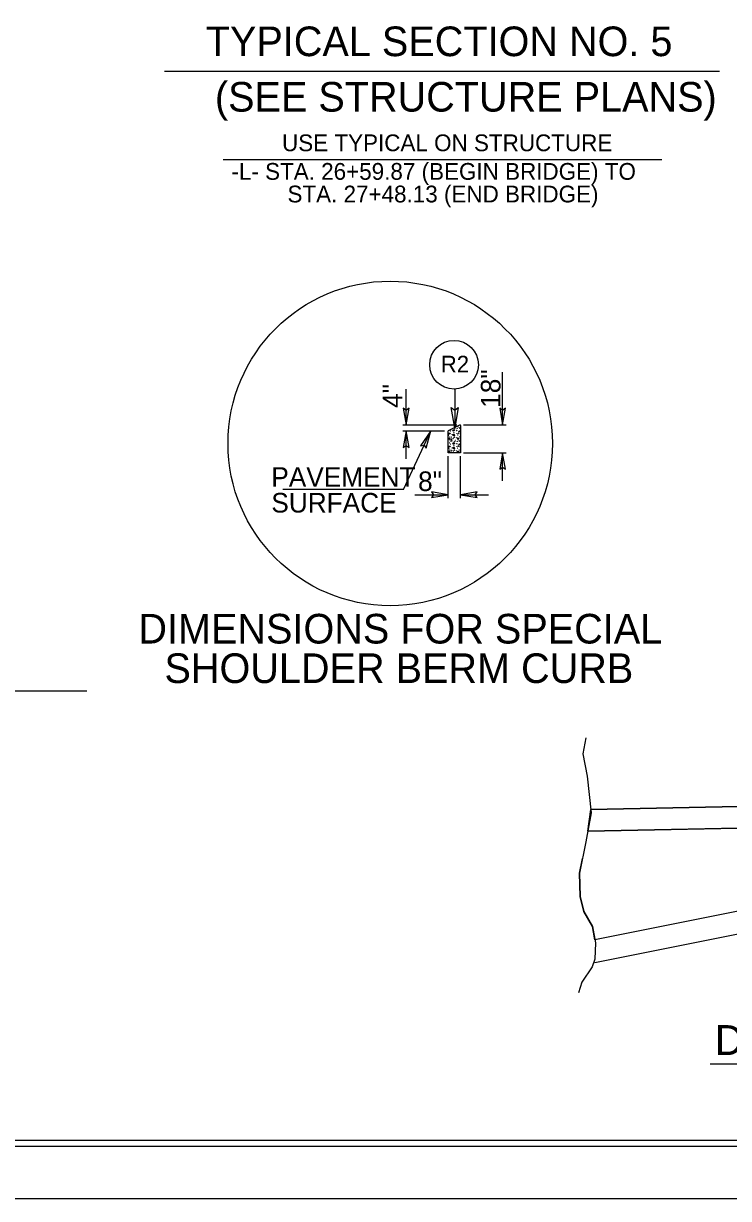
# Model space of a CAD drawing. Extents: x 573687 to 575553, y -54556 to -52223.
# Drawn here: x 574539 to 574841, y -53323 to -52818 of the extents above; entities that cross this region are included whole.
import ezdxf

# ---------------------------------------------------------------- set-up
doc = ezdxf.new("R2010")
doc.units = 0
for name, color, linetype in [('Old_Level_1', 7, 'Continuous'), ('Old_Level_11', 7, 'Continuous'), ('Old_Level_3', 7, 'Continuous'), ('Old_Level_7', 7, 'Continuous'), ('Prop Dimension', 7, 'Continuous'), ('Prop Dimension Text', 7, 'Continuous'), ('Sheet Cutting Line CELL', 7, 'Continuous'), ('Sheet Plot Border Inside CELL', 7, 'Continuous'), ('Sheet Plot Border Outside CELL', 7, 'Continuous'), ('Sheet Typical CELL', 7, 'Continuous'), ('Typical Detail Wedge2 CELL', 7, 'Continuous'), ('Typical Guardrail CELL', 7, 'Continuous'), ('Typical Terminator CELL', 7, 'Continuous'), ('Typical Text Label CELL', 7, 'Continuous')]:
    doc.layers.add(name, color=color, linetype=linetype)

msp = doc.modelspace()

# ---------------------------------------------------------------- linework, layer by layer
at = {"layer": 'Old_Level_1'}
for p, q in [((574727.78, -52990.69), (574745.99, -52990.69)), ((574727.78, -53002.62), (574745.99, -53002.62))]:
    msp.add_line(p, q, dxfattribs=at)
msp.add_circle((574696.27, -52998.62), 69.64, dxfattribs=at)
at = {"layer": 'Old_Level_11'}
for q in [(574713.69, -52993.27), (574650.16, -53018.42)]:
    msp.add_line((574701.93, -53018.42), q, dxfattribs=at)
msp.add_lwpolyline([(574711.68, -53000.72), (574713.69, -52993.27), (574709.26, -52999.59), (574710.87, -52999.31)], close=True, dxfattribs=at)
at = {"layer": 'Old_Level_3'}
for points in [[(574726.45, -52990.86), (574726.28, -52990.69), (574721.12, -52993.27)], [(574726.45, -52990.86), (574726.45, -53002.62), (574721.12, -53002.62), (574721.12, -52993.27)]]:
    msp.add_lwpolyline(points, dxfattribs=at)
msp.add_arc((574721.09, -52997.75), 0.0586, 309.7979, 50.2021, dxfattribs=at)
at = {"layer": 'Old_Level_7'}
msp.add_line((574725.67, -53002.1), (574725.43, -53002.62), dxfattribs=at)
for points in [[(574723.76, -52993.26), (574723.19, -52993.32), (574723.61, -52992.66), (574723.78, -52992.86)], [(574721.72, -52996.36), (574721.78, -52996.94), (574721.13, -52996.51), (574721.32, -52996.34)], [(574721.5, -52994.66), (574721.16, -52994.19), (574721.94, -52994.23), (574721.86, -52994.47)], [(574723.46, -52995.15), (574724.04, -52995.38), (574723.79, -52994.8), (574723.3, -52994.83)], [(574725.67, -52996.48), (574725.43, -52997.01), (574725.08, -52996.32), (574725.33, -52996.27)], [(574721.72, -53001.98), (574721.78, -53002.55), (574721.13, -53002.13), (574721.32, -53001.96)], [(574721.5, -53000.27), (574721.16, -52999.8), (574721.94, -52999.84), (574721.86, -53000.09)], [(574723.76, -52998.87), (574723.19, -52998.93), (574723.61, -52998.27), (574723.78, -52998.47)], [(574723.46, -53000.76), (574724.04, -53000.99), (574723.79, -53000.41), (574723.3, -53000.44)]]:
    msp.add_lwpolyline(points, close=True, dxfattribs=at)
for points in [[(574725.6, -52991.03), (574725.43, -52991.4), (574725.31, -52991.17)], [(574726.45, -52993.69), (574726.33, -52993.94), (574725.98, -52993.24), (574726.23, -52993.2), (574726.45, -52993.33)], [(574725.42, -53002.62), (574725.08, -53001.93), (574725.33, -53001.88), (574725.67, -53002.1)], [(574726.45, -52999.3), (574726.33, -52999.55), (574725.98, -52998.86), (574726.23, -52998.81), (574726.45, -52998.95)]]:
    msp.add_lwpolyline(points, dxfattribs=at)
for centre, radius in [((574723.93, -52992.11), 0.0586), ((574724.83, -52993.1), 0.0586), ((574725.06, -52992.09), 0.0586), ((574725.85, -52991.73), 0.0622), ((574726.24, -52992.14), 0.0586), ((574721.39, -52995.07), 0.0586), ((574721.86, -52997.37), 0.0622), ((574721.87, -52995.83), 0.0636), ((574722.15, -52993.32), 0.0586), ((574722.41, -52997.72), 0.0586), ((574722.52, -52996.74), 0.0631), ((574722.64, -52995.93), 0.0586), ((574722.67, -52997.13), 0.0586), ((574722.67, -52997.6), 0.0586), ((574722.87, -52994.92), 0.0586), ((574723.33, -52996.48), 0.0586), ((574723.45, -52997.11), 0.0394), ((574723.55, -52994.01), 0.0586), ((574723.81, -52995.98), 0.0586), ((574723.93, -52997.72), 0.0586), ((574724.19, -52997.37), 0.0586), ((574724.8, -52996.2), 0.0586), ((574724.86, -52994.29), 0.0586), ((574725.06, -52997.7), 0.0586), ((574725.24, -52995.06), 0.0586), ((574725.52, -52993.65), 0.0586), ((574725.64, -52994.27), 0.0394), ((574725.85, -52997.35), 0.0622), ((574725.86, -52995.8), 0.0636), ((574726.24, -52997.76), 0.0586), ((574726.38, -52994.53), 0.0586), ((574721.39, -53000.69), 0.0586), ((574721.58, -52998.37), 0.0586), ((574721.87, -53001.44), 0.0636), ((574722.15, -52998.94), 0.0586), ((574722.52, -53002.35), 0.0631), ((574722.64, -53001.55), 0.0586), ((574722.87, -53000.53), 0.0586), ((574723.33, -53002.1), 0.0586), ((574723.55, -52999.63), 0.0586), ((574723.81, -53001.59), 0.0586), ((574724.8, -53001.81), 0.0586), ((574724.83, -52998.71), 0.0586), ((574724.86, -52999.91), 0.0586), ((574725.24, -53000.67), 0.0586), ((574725.52, -52999.26), 0.0586), ((574725.64, -52999.89), 0.0394), ((574725.86, -53001.42), 0.0636), ((574726.38, -53000.15), 0.0586)]:
    msp.add_circle(centre, radius, dxfattribs=at)
for centre, radius, start, end in [((574724.19, -52991.75), 0.0586, 193.5972, 39.5125), ((574726.5, -52991.1), 0.0631, 157.2508, 202.7492), ((574726.5, -52996.72), 0.0631, 157.2508, 202.7492), ((574726.5, -53002.33), 0.0631, 157.2508, 202.7492)]:
    msp.add_arc(centre, radius, start, end, dxfattribs=at)
at = {"layer": 'Prop Dimension'}
for p, q in [((574744.49, -52990.69), (574744.49, -52967.99)), ((574703.12, -52990.69), (574703.12, -52975.4)), ((574724.03, -52975.32), (574724.03, -52991.88)), ((574701.62, -52990.69), (574724.78, -52990.69)), ((574701.62, -52993.27), (574719.62, -52993.27)), ((574703.12, -53005.27), (574703.12, -52993.27)), ((574744.49, -53014.62), (574744.49, -53002.62)), ((574721.12, -53022.12), (574721.12, -53004.12)), ((574726.45, -53022.12), (574726.45, -53004.12)), ((574706.85, -53020.62), (574721.12, -53020.62)), ((574726.45, -53020.62), (574738.45, -53020.62))]:
    msp.add_line(p, q, dxfattribs=at)
msp.add_lwpolyline([(575015.22, -53165.42), (575015.22, -53151.04), (575015.22, -53151.04), (574782.37, -53155.69), (574782.34, -53155.91), (574782.48, -53157.18), (574781.08, -53164.8), (574781.05, -53165.05), (574945.34, -53161.76), (574980.06, -53161.07), (574994.79, -53160.77), (575000.02, -53168.44), (575014.87, -53165.35), (575015.22, -53165.42), (575015.22, -53165.42)], dxfattribs=at)
msp.add_circle((574723.65, -52964.87), 10.46, dxfattribs=at)
at = {"layer": 'Prop Dimension Text'}
for p, q in [((574599.38, -52838.84), (574837.58, -52838.84)), ((574624.61, -52876.84), (574812.83, -52876.84)), ((574291.33, -53104.87), (574566.09, -53104.87)), ((574833.54, -53264.81), (575194.71, -53264.81))]:
    msp.add_line(p, q, dxfattribs=at)
at = {"layer": 'Sheet Cutting Line CELL'}
msp.add_line((573687.43, -53322.67), (575371.43, -53322.67), dxfattribs=at)
at = {"layer": 'Sheet Plot Border Inside CELL'}
msp.add_lwpolyline([(575366.93, -52245.12), (573700.43, -52245.12), (573700.43, -53300.22), (575366.93, -53300.22)], close=True, dxfattribs=at)
at = {"layer": 'Sheet Plot Border Outside CELL'}
msp.add_lwpolyline([(575371.43, -52222.67), (573687.43, -52222.67), (573687.43, -53322.67), (575371.43, -53322.67)], close=True, dxfattribs=at)
at = {"layer": 'Sheet Typical CELL'}
msp.add_lwpolyline([(575354.43, -52247.67), (573854.43, -52247.67), (573854.43, -53297.67), (575354.43, -53297.67)], close=True, dxfattribs=at)
at = {"layer": 'Typical Detail Wedge2 CELL'}
for p, q in [((575015.22, -53151.04), (574782.37, -53155.69)), ((574782.37, -53155.69), (575015.22, -53151.04)), ((574781.05, -53165.05), (574782.37, -53155.69)), ((574994.79, -53160.77), (574781.05, -53165.05)), ((574994.79, -53160.77), (574781.05, -53165.05)), ((575000.02, -53168.44), (574784.12, -53211.67)), ((575015.13, -53175.32), (574784.04, -53221.54))]:
    msp.add_line(p, q, dxfattribs=at)
for points in [[(574780.21, -53124.96), (574778.97, -53131.78), (574780.83, -53141.48), (574782.48, -53157.18), (574780.21, -53169.57), (574777.53, -53183), (574777.73, -53193.12), (574779.39, -53199.52), (574783.11, -53205.93), (574784.34, -53212.95), (574784.14, -53219.97), (574782.9, -53223.28), (574778.56, -53229.89), (574777.12, -53234.43)], [(574784.11, -53211.66), (574783.11, -53205.93), (574779.39, -53199.52), (574777.73, -53193.12), (574777.53, -53183), (574778.77, -53176.77)]]:
    msp.add_lwpolyline(points, dxfattribs=at)
at = {"layer": 'Typical Guardrail CELL'}
for points in [[(574701.87, -52983.56), (574703.12, -52990.69), (574704.38, -52983.56), (574703.12, -52984.44)], [(574743.24, -52983.56), (574744.49, -52990.69), (574745.75, -52983.56), (574744.49, -52984.44)], [(574704.38, -53000.4), (574703.12, -52993.27), (574701.87, -53000.4), (574703.12, -52999.52)], [(574745.75, -53009.74), (574744.49, -53002.62), (574743.24, -53009.74), (574744.49, -53008.87)], [(574714, -53021.87), (574721.12, -53020.62), (574714, -53019.37), (574714.87, -53020.62)], [(574733.58, -53019.37), (574726.45, -53020.62), (574733.58, -53021.87), (574732.7, -53020.62)]]:
    msp.add_lwpolyline(points, close=True, dxfattribs=at)
at = {"layer": 'Typical Terminator CELL'}
msp.add_lwpolyline([(574725.44, -52983.26), (574724.03, -52991.88), (574722.42, -52983.24), (574723.96, -52984.32)], close=True, dxfattribs=at)

# ---------------------------------------------------------------- texts
at = {"layer": 'Prop Dimension Text'}
msp.add_text('R2', height=7.113, dxfattribs=at).set_placement((574717.95, -52968.12))
at = {"layer": 'Typical Text Label CELL'}
for s, height, rotation, p in [('TYPICAL SECTION NO. 5', 12.7159, 0.0001, (574617.08, -52832.42)), ('(SEE STRUCTURE PLANS)', 12.7159, 0.0001, (574621, -52856.22)), ('USE TYPICAL ON STRUCTURE', 7.2, 360, (574649.82, -52873.22)), ('-L- STA. 26+59.87 (BEGIN BRIDGE) TO', 7.2, 360, (574628.1, -52885.48)), ('STA. 27+48.13 (END BRIDGE)', 7.2, 360, (574652.15, -52895.19)), ('18"', 8.415, 90, (574743.59, -52983.35)), ('4"', 8.415, 90, (574701.42, -52983.38)), ('DIMENSIONS FOR SPECIAL', 12.7159, 360, (574588.15, -53084.49)), ('SHOULDER BERM CURB', 12.7159, 360, (574599.35, -53101.44)), ('DETAIL SHOWING METHOD OF WEDGING', 12.8401, 0.0001, (574835.6, -53261.09))]:
    msp.add_text(s, height=height, rotation=rotation, dxfattribs=at).set_placement(p)
for s, p in [('PAVEMENT', (574645.22, -53017.25)), ('8"', (574708.22, -53019.06)), ('SURFACE', (574645.22, -53028.28))]:
    msp.add_text(s, height=8.415, dxfattribs=at).set_placement(p)

doc.saveas('drawing.dxf')
